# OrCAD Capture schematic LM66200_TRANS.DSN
size C; title: LM66200: 1.6 V to 5 V, 2.5-A Dual Ideal Diode with Automatic; rev: 1.0; note: Datasheet: SLVSG04     EVM: PSIL122; note: Switchover
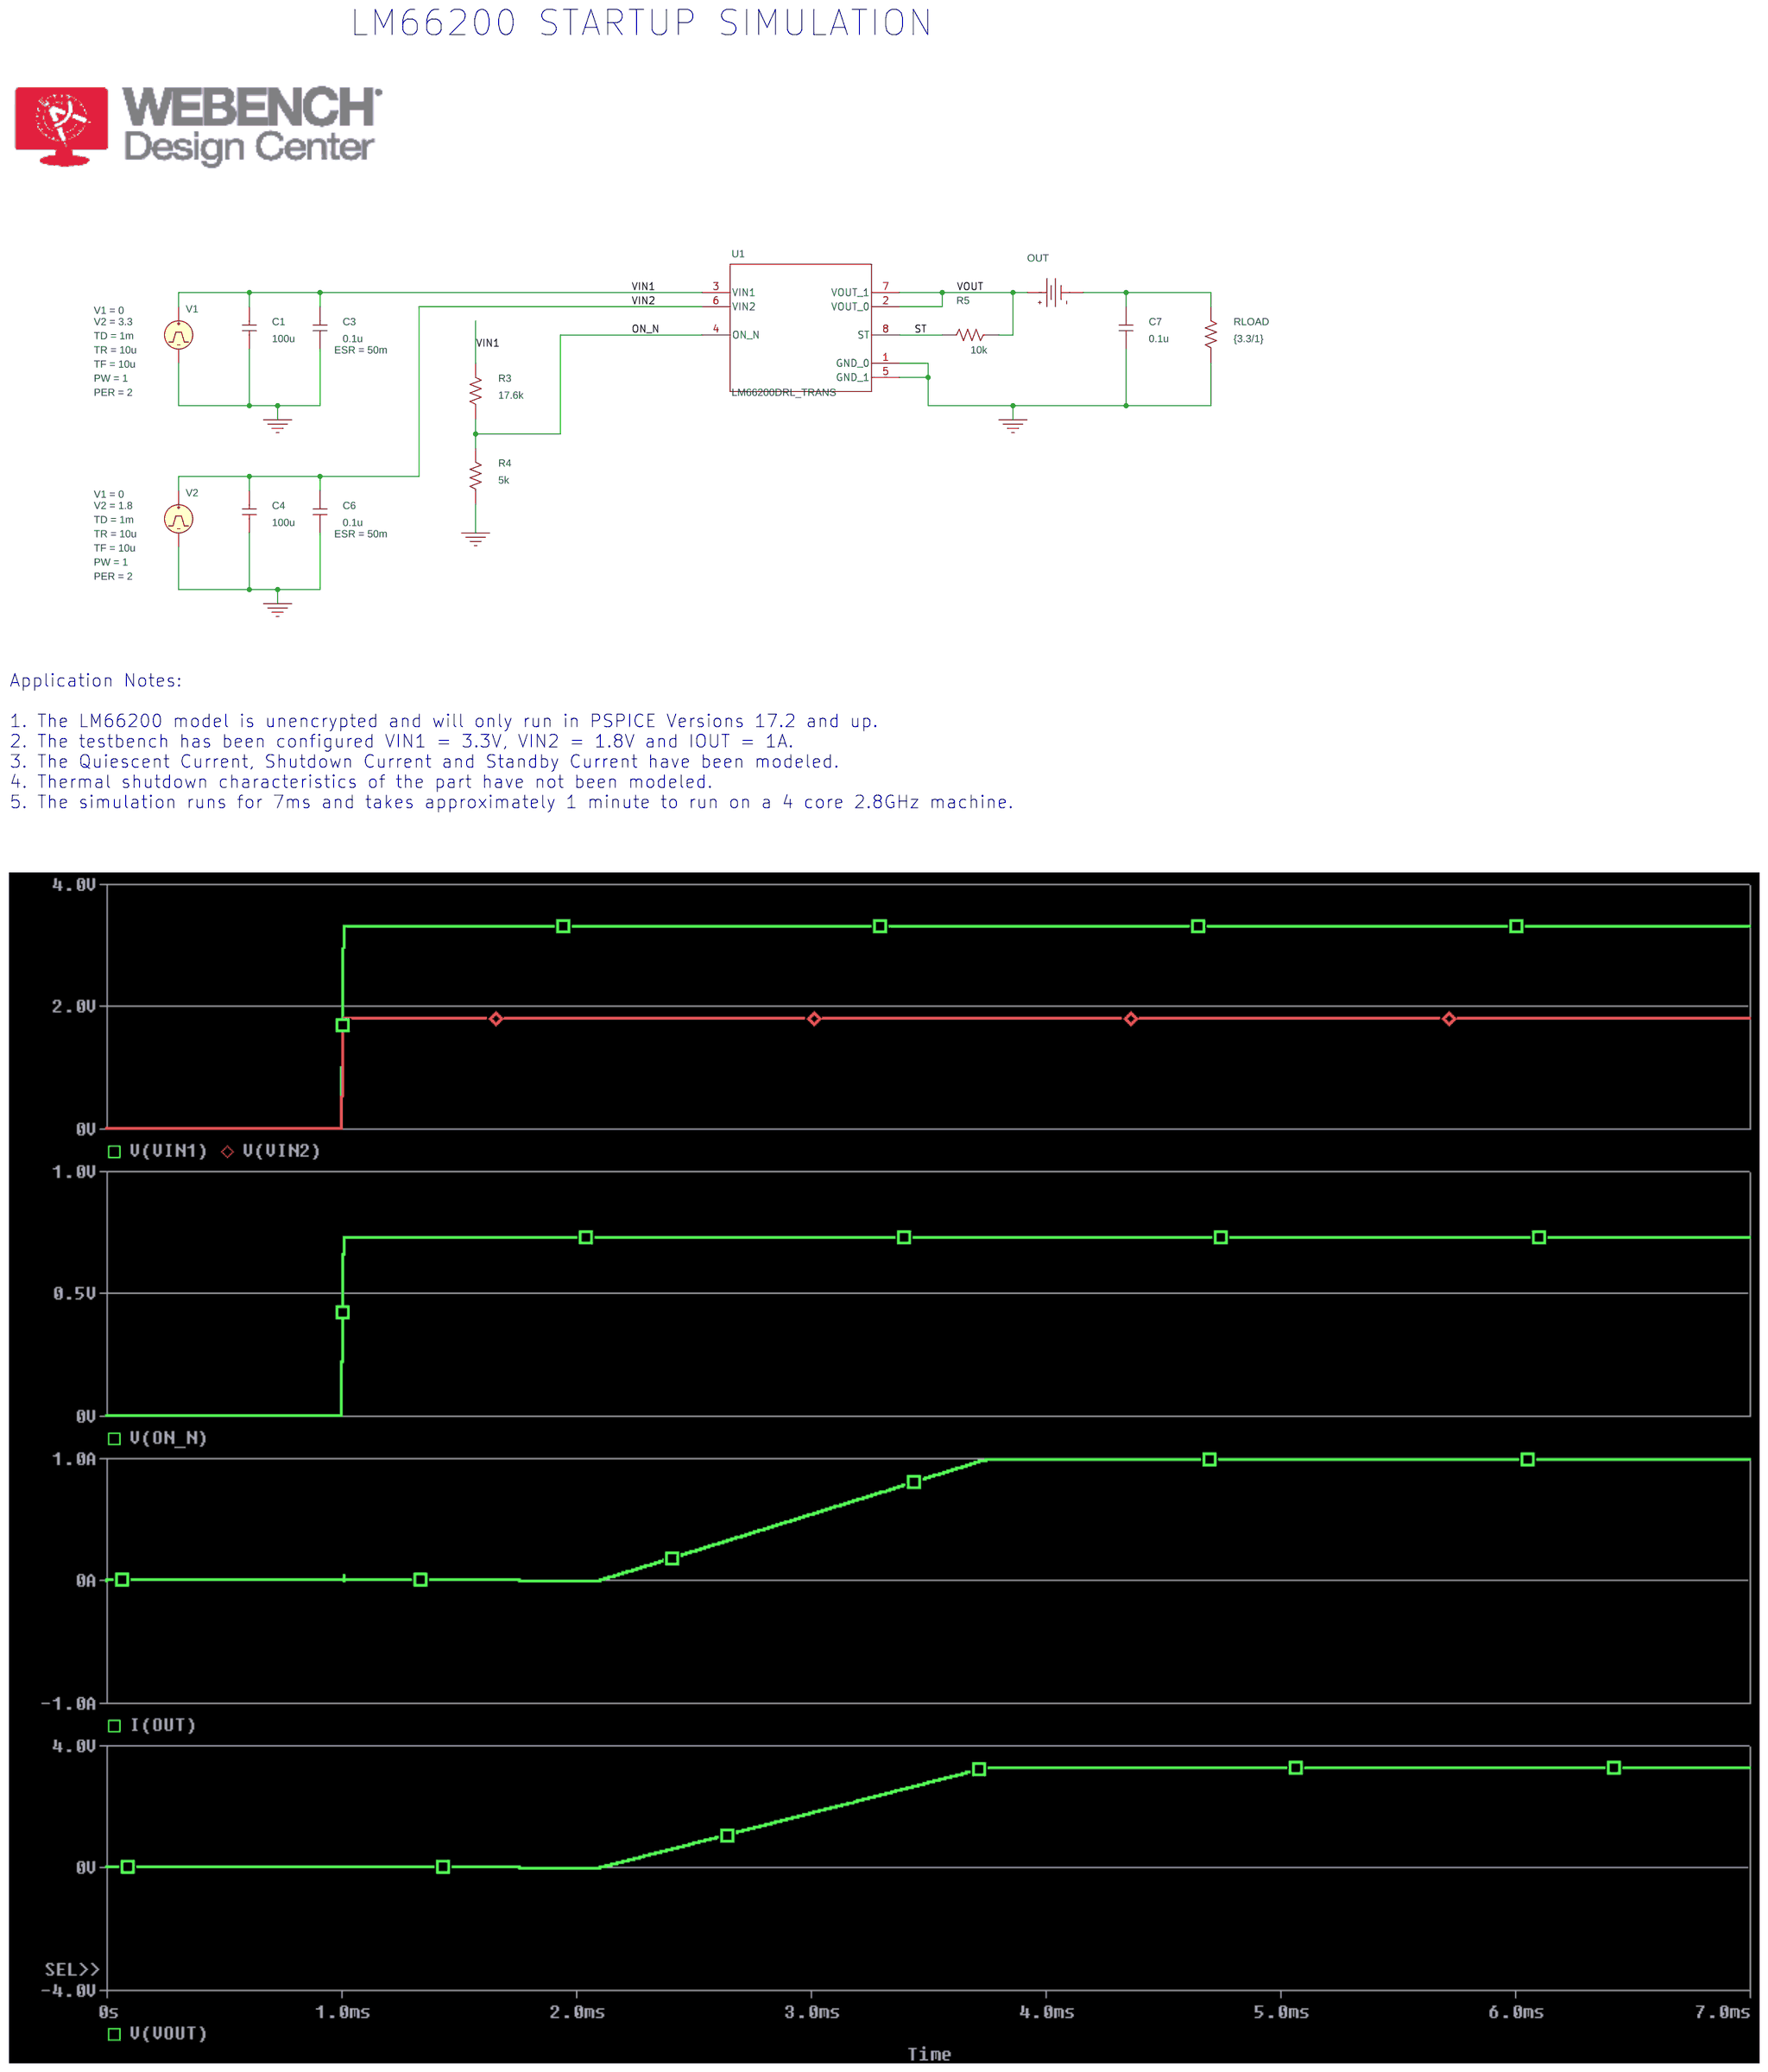
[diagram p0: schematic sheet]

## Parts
C1  100u  [RAD/CK05]
C3  0.1u  [RAD/CK05]
C4  100u  [RAD/CK05]
C6  0.1u  [RAD/CK05]
C7  0.1u  [RAD/CK05]
OUT  VDC
R3  17.6k  [AX/RC05]
R4  5k  [AX/RC05]
R5  10k  [AX/RC05]
RLOAD  {3.3/1}  [AX/RC05]
U1  LM66200DRL_TRANS  [DRL0008A-MFG]
V1  VPULSE
V2  VPULSE

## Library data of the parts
C1 C4 C7 = C
C3 C6 = C: AppProp: InductiveSlave:;SRF:;PrevCap:0.1u;PrevESL:; ESR: 50m
OUT = VDC
R3-R5 RLOAD = R
U1 = LM66200DRL_TRANS
V1 = VPULSE: PER: 2; PW: 1; TD: 1m; TF: 10u; TR: 10u; V1: 0; V2: 3.3
V2 = VPULSE: PER: 2; PW: 1; TD: 1m; TF: 10u; TR: 10u; V1: 0; V2: 1.8

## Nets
VIN1: C1.2 C3.2 R3.2 U1.3(VIN1) V1.1(+)
VIN2: C4.2 C6.2 U1.6(VIN2) V2.1(+)
0: C1.1 C3.1 C4.1 C6.1 C7.1 R4.1 RLOAD.1 U1.1(GND_0) U1.5(GND_1) V1.2(-) V2.2(-)
ON_N: R3.1 R4.2 U1.4(ON_N)
ST: R5.2 U1.8(ST)
VOUT: OUT.0(+) R5.1 U1.2(VOUT_0) U1.7(VOUT_1)
N16665815: C7.2 OUT.1(-) RLOAD.2

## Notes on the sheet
- LM66200 STARTUP SIMULATION
- Application Notes:
  1. The LM66200 model is unencrypted and will only run in PSPICE Versions 17.2 and up.
  2. The testbench has been configured VIN1 = 3.3V, VIN2 = 1.8V and IOUT = 1A.
  3. The Quiescent Current, Shutdown Current and Standby Current have been modeled.
  4. Thermal shutdown characteristics of the part have not been modeled.
  5. The simulation runs for 7ms and takes approximately 1 minute to run on a 4 core 2.8GHz machine.
